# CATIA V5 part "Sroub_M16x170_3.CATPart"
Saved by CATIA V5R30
Part number: Sroub_M16x170_3
Definition: E 1200_16x170
Nomenclature: E 1200_16x170
Source: Unknown
Description: PART--DESC
Bounding box of the stored display mesh (mm): x 128 to 152, y -148.99 to -125.01, z -259 to -73
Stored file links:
  E:\Bakalarka\Model\Forma_v7\Sroub_M16x170_3.CATPart
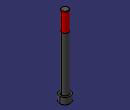
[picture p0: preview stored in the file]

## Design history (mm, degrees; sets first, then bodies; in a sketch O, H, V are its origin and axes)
Body1 "MANIFOLD_SOLID_BREP #3810" (main body)
  Solid1: solid without history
